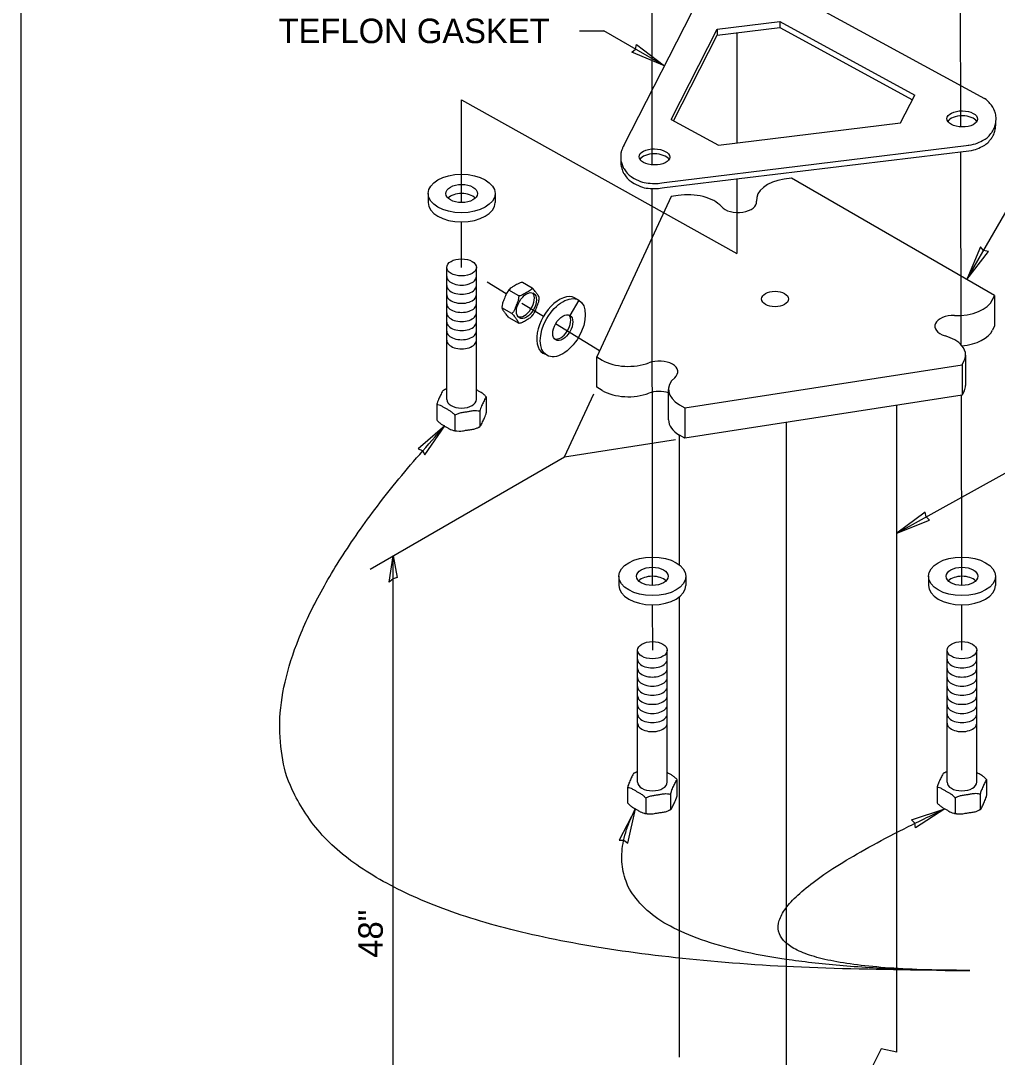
# Model space of a CAD drawing. Extents: x 99862 to 103151, y 99997 to 117076.
# Drawn here: x 99862 to 100500, y 115528 to 116205 of the extents above; entities that cross this region are included whole.
import ezdxf

# ---------------------------------------------------------------- set-up
doc = ezdxf.new("R2010")
doc.units = 0
for name, color, linetype in [('Level 1', 7, 'Continuous'), ('Level 12', 7, 'Continuous'), ('Level 13', 7, 'Continuous'), ('Level 15', 7, 'Continuous'), ('Level 20', 7, 'Continuous'), ('Level 4', 7, 'Continuous'), ('Level 6', 7, 'Continuous'), ('Level 8', 7, 'Continuous')]:
    doc.layers.add(name, color=color, linetype=linetype)

msp = doc.modelspace()

# ---------------------------------------------------------------- linework, layer by layer
at = {"layer": 'Level 1'}
msp.add_lwpolyline([(99862, 114999.5), (103151, 114999.5), (103151, 117075.5), (99862, 117075.5)], close=True, dxfattribs=at)
at = {"layer": 'Level 12'}
for p, q in [((100128.34, 116092.36), (100128.34, 116086.41)), ((100172.05, 116092.36), (100172.05, 116086.41)), ((100140.48, 115957.85), (100140.48, 116044.09)), ((100159.91, 115957.85), (100159.91, 116044.09)), ((100166.45, 115949.46), (100166.45, 115959.38)), ((100133.95, 115954.35), (100133.95, 115944.44)), ((100162.09, 115950), (100162.09, 115940.08)), ((100145.84, 115947.48), (100145.84, 115937.57)), ((100253.06, 115842.29), (100253.06, 115836.34)), ((100296.76, 115842.29), (100296.76, 115836.34)), ((100455.44, 115842.29), (100455.44, 115836.34)), ((100499.14, 115842.29), (100499.14, 115836.34)), ((100265.2, 115707.78), (100265.2, 115794.02)), ((100284.62, 115707.78), (100284.62, 115794.02)), ((100467.58, 115707.78), (100467.58, 115794.02)), ((100487, 115707.78), (100487, 115794.02)), ((100291.16, 115699.39), (100291.16, 115709.3)), ((100493.54, 115699.39), (100493.54, 115709.3)), ((100258.66, 115704.28), (100258.66, 115694.36)), ((100286.81, 115699.92), (100286.81, 115690.01)), ((100461.04, 115704.28), (100461.04, 115694.36)), ((100489.18, 115699.92), (100489.18, 115690.01)), ((100270.56, 115697.41), (100270.56, 115687.5)), ((100472.94, 115697.41), (100472.94, 115687.5))]:
    msp.add_line(p, q, dxfattribs=at)
for centre, major_axis in [((100150.2, 116092.36), (-21.85, 0)), ((100150.2, 116092.36), (-10.32, 0)), ((100150.2, 116044.09), (-9.71, 0)), ((100274.91, 115842.29), (-21.85, 0)), ((100477.29, 115842.29), (-21.85, 0)), ((100274.91, 115842.29), (-10.32, 0)), ((100477.29, 115842.29), (-10.32, 0)), ((100274.91, 115794.02), (-9.71, 0)), ((100477.29, 115794.02), (-9.71, 0))]:
    msp.add_ellipse(centre, major_axis=major_axis, ratio=0.57735, dxfattribs=at)
for centre, major_axis, start_param, end_param in [((100150.2, 116086.41), (-10.32, 0), 3.664192, 5.760586), ((100150.2, 116086.41), (21.85, 0), 3.141593, 6.283185), ((100150.2, 116038.15), (9.71, 0), 3.141588, 6.283185), ((100150.2, 116032.2), (9.71, 0), 3.141588, 6.283185), ((100150.2, 116026.25), (9.71, 0), 3.141588, 6.283185), ((100150.2, 116020.31), (9.71, 0), 3.141588, 6.283185), ((100150.2, 116014.36), (9.71, 0), 3.141588, 6.283185), ((100150.2, 116008.41), (9.71, 0), 3.141588, 6.283185), ((100150.2, 116002.46), (9.71, 0), 3.141588, 6.283185), ((100150.2, 115996.52), (9.71, 0), 3.141588, 6.283185), ((100150.2, 115957.85), (9.71, 0), 3.141593, 6.283185), ((100274.91, 115836.34), (-10.32, 0), 3.664192, 5.760586), ((100477.29, 115836.34), (-10.32, 0), 3.664192, 5.760586), ((100274.91, 115836.34), (21.85, 0), 3.141593, 6.283185), ((100477.29, 115836.34), (21.85, 0), 3.141593, 6.283185), ((100274.91, 115788.07), (9.71, 0), 3.141588, 6.283185), ((100477.29, 115788.07), (9.71, 0), 3.141588, 6.283185), ((100274.91, 115782.13), (9.71, 0), 3.141588, 6.283185), ((100477.29, 115782.13), (9.71, 0), 3.141588, 6.283185), ((100274.91, 115776.18), (9.71, 0), 3.141588, 6.283185), ((100477.29, 115776.18), (9.71, 0), 3.141588, 6.283185), ((100274.91, 115770.23), (9.71, 0), 3.141588, 6.283185), ((100477.29, 115770.23), (9.71, 0), 3.141588, 6.283185), ((100274.91, 115764.28), (9.71, 0), 3.141588, 6.283185), ((100477.29, 115764.28), (9.71, 0), 3.141588, 6.283185), ((100274.91, 115758.34), (9.71, 0), 3.141588, 6.283185), ((100477.29, 115758.34), (9.71, 0), 3.141588, 6.283185), ((100274.91, 115752.39), (9.71, 0), 3.141588, 6.283185), ((100477.29, 115752.39), (9.71, 0), 3.141588, 6.283185), ((100274.91, 115746.44), (9.71, 0), 3.141588, 6.283185), ((100477.29, 115746.44), (9.71, 0), 3.141588, 6.283185), ((100274.91, 115707.78), (9.71, 0), 3.141593, 6.283185), ((100477.29, 115707.78), (9.71, 0), 3.141593, 6.283185)]:
    msp.add_ellipse(centre, major_axis=major_axis, ratio=0.57735, start_param=start_param, end_param=end_param, dxfattribs=at)
for points, degree in [([(100138.18, 115963.68), (100138.12, 115963.65), (100138.05, 115963.59), (100137.43, 115962.93), (100136.72, 115961.31), (100136.12, 115960.03), (100135.53, 115958.74), (100134.82, 115957.29), (100134.15, 115955.14), (100134.04, 115954.75), (100133.95, 115954.35)], 3), ([(100138.9, 115964.1), (100138.68, 115963.98), (100138.47, 115963.86), (100138.24, 115963.72), (100138.21, 115963.7), (100138.18, 115963.68)], 3), ([(100140.48, 115964.77), (100140.13, 115964.65), (100139.78, 115964.52), (100139.27, 115964.29), (100139.09, 115964.2), (100138.9, 115964.1)], 3), ([(100166.45, 115959.38), (100166.19, 115959.72), (100165.88, 115960.05), (100164.07, 115961.82), (100162.12, 115962.86), (100160.5, 115963.8), (100160.31, 115963.91), (100160.11, 115964.02), (100159.91, 115964.14)], 3), ([(100166.45, 115959.38), (100166.35, 115959.37), (100166.24, 115959.28), (100165.58, 115958.57), (100164.86, 115956.95), (100164.27, 115955.67), (100163.67, 115954.39), (100162.96, 115952.94), (100162.3, 115950.79), (100162.19, 115950.39), (100162.09, 115950)], 3), ([(100145.84, 115947.48), (100145.58, 115947.83), (100145.28, 115948.16), (100143.47, 115949.92), (100141.52, 115950.96), (100139.9, 115951.9), (100138.27, 115952.84), (100136.32, 115954.05), (100134.51, 115954.37), (100134.21, 115954.39), (100133.95, 115954.35)], 3), ([(100162.09, 115950), (100161.74, 115950.14), (100161.32, 115950.23), (100158.85, 115950.56), (100156.19, 115950.07), (100153.97, 115949.72), (100151.75, 115949.38), (100149.09, 115949.05), (100146.61, 115947.95), (100146.2, 115947.73), (100145.84, 115947.48)], 3), ([(100133.95, 115944.44), (100134.21, 115944.09), (100134.51, 115943.76), (100136.32, 115942), (100138.27, 115940.96), (100139.9, 115940.02), (100141.5, 115939.09), (100143.41, 115937.91), (100144.94, 115937.61)], 3), ([(100162.22, 115940.13), (100162.28, 115940.17), (100162.34, 115940.22), (100162.96, 115940.88), (100163.67, 115942.51), (100164.27, 115943.79), (100164.86, 115945.07), (100165.58, 115946.52), (100166.24, 115948.67), (100166.35, 115949.07), (100166.45, 115949.46)], 3), ([(100144.93, 115937.61), (100145.68, 115937.46), (100146.44, 115937.35), (100147.18, 115937.26)], 2), ([(100144.94, 115937.61), (100144.96, 115937.6), (100144.98, 115937.6), (100145.28, 115937.54), (100145.58, 115937.52), (100145.84, 115937.57)], 3), ([(100145.84, 115937.57), (100146.2, 115937.43), (100146.61, 115937.34), (100147.05, 115937.28), (100147.12, 115937.27), (100147.18, 115937.26)], 3), ([(100147.18, 115937.26), (100149.25, 115937.03), (100151.82, 115937.51), (100153.97, 115937.84), (100156.19, 115938.18), (100158.85, 115938.51), (100161.12, 115939.53), (100161.31, 115939.62), (100161.49, 115939.72)], 3), ([(100161.49, 115939.71), (100161.71, 115939.83), (100161.92, 115939.95), (100162.16, 115940.09), (100162.19, 115940.11), (100162.22, 115940.13)], 3), ([(100161.49, 115939.72), (100161.7, 115939.83), (100161.9, 115939.95), (100162.09, 115940.08)], 2), ([(100162.09, 115940.08), (100162.13, 115940.09), (100162.17, 115940.1), (100162.22, 115940.13)], 2), ([(100262.89, 115713.61), (100262.83, 115713.57), (100262.77, 115713.52), (100262.15, 115712.86), (100261.43, 115711.23), (100260.84, 115709.95), (100260.25, 115708.67), (100259.53, 115707.22), (100258.87, 115705.07), (100258.76, 115704.67), (100258.66, 115704.28)], 3), ([(100263.62, 115714.03), (100263.4, 115713.91), (100263.19, 115713.79), (100262.95, 115713.65), (100262.92, 115713.63), (100262.89, 115713.61)], 3), ([(100265.2, 115714.7), (100264.84, 115714.58), (100264.49, 115714.44), (100263.99, 115714.22), (100263.8, 115714.13), (100263.62, 115714.03)], 3), ([(100291.16, 115709.3), (100290.9, 115709.65), (100290.6, 115709.98), (100288.79, 115711.74), (100286.84, 115712.78), (100285.21, 115713.72), (100285.02, 115713.83), (100284.82, 115713.95), (100284.62, 115714.06)], 3), ([(100465.27, 115713.61), (100465.21, 115713.57), (100465.15, 115713.52), (100464.53, 115712.86), (100463.81, 115711.23), (100463.22, 115709.95), (100462.62, 115708.67), (100461.91, 115707.22), (100461.25, 115705.07), (100461.14, 115704.67), (100461.04, 115704.28)], 3), ([(100465.99, 115714.03), (100465.77, 115713.91), (100465.56, 115713.79), (100465.33, 115713.65), (100465.3, 115713.63), (100465.27, 115713.61)], 3), ([(100467.58, 115714.7), (100467.22, 115714.58), (100466.87, 115714.44), (100466.36, 115714.22), (100466.18, 115714.13), (100466, 115714.03)], 3), ([(100493.54, 115709.3), (100493.28, 115709.65), (100492.97, 115709.98), (100491.16, 115711.74), (100489.22, 115712.78), (100487.59, 115713.72), (100487.4, 115713.83), (100487.2, 115713.95), (100487, 115714.06)], 3), ([(100286.81, 115699.92), (100286.9, 115700.32), (100287.01, 115700.72), (100287.68, 115702.86), (100288.39, 115704.32), (100288.98, 115705.6), (100289.58, 115706.88), (100290.29, 115708.5), (100290.95, 115709.21), (100291.07, 115709.29), (100291.16, 115709.3)], 3), ([(100493.54, 115709.3), (100493.44, 115709.29), (100493.33, 115709.21), (100492.67, 115708.5), (100491.96, 115706.88), (100491.36, 115705.6), (100490.77, 115704.32), (100490.05, 115702.86), (100489.39, 115700.72), (100489.28, 115700.32), (100489.18, 115699.92)], 3), ([(100258.66, 115704.28), (100258.92, 115704.32), (100259.23, 115704.3), (100261.04, 115703.98), (100262.99, 115702.77), (100264.61, 115701.83), (100266.24, 115700.89), (100268.18, 115699.85), (100269.99, 115698.08), (100270.3, 115697.75), (100270.56, 115697.41)], 3), ([(100270.56, 115697.41), (100270.91, 115697.66), (100271.33, 115697.88), (100273.8, 115698.98), (100276.46, 115699.31), (100278.68, 115699.65), (100280.9, 115699.99), (100283.56, 115700.49), (100286.04, 115700.15), (100286.45, 115700.06), (100286.81, 115699.92)], 3), ([(100472.94, 115697.41), (100472.68, 115697.75), (100472.37, 115698.08), (100470.56, 115699.85), (100468.61, 115700.89), (100466.99, 115701.83), (100465.36, 115702.77), (100463.41, 115703.98), (100461.6, 115704.3), (100461.3, 115704.32), (100461.04, 115704.28)], 3), ([(100489.18, 115699.92), (100488.83, 115700.06), (100488.41, 115700.15), (100485.94, 115700.49), (100483.28, 115699.99), (100481.06, 115699.65), (100478.84, 115699.31), (100476.18, 115698.98), (100473.71, 115697.88), (100473.29, 115697.66), (100472.94, 115697.41)], 3), ([(100258.66, 115694.36), (100258.92, 115694.02), (100259.23, 115693.69), (100261.04, 115691.92), (100262.99, 115690.88), (100264.61, 115689.94), (100266.21, 115689.02), (100268.13, 115687.83), (100269.65, 115687.53)], 3), ([(100286.93, 115690.06), (100286.99, 115690.09), (100287.05, 115690.15), (100287.68, 115690.81), (100288.39, 115692.43), (100288.98, 115693.71), (100289.58, 115695), (100290.29, 115696.45), (100290.95, 115698.6), (100291.07, 115698.99), (100291.16, 115699.39)], 3), ([(100461.04, 115694.36), (100461.3, 115694.02), (100461.6, 115693.69), (100463.41, 115691.92), (100465.36, 115690.88), (100466.99, 115689.94), (100468.59, 115689.02), (100470.5, 115687.83), (100472.03, 115687.53)], 3), ([(100489.31, 115690.06), (100489.37, 115690.09), (100489.43, 115690.15), (100490.05, 115690.81), (100490.77, 115692.43), (100491.36, 115693.71), (100491.96, 115695), (100492.67, 115696.45), (100493.33, 115698.6), (100493.44, 115698.99), (100493.54, 115699.39)], 3), ([(100269.65, 115687.53), (100270.4, 115687.39), (100271.16, 115687.27), (100271.9, 115687.19)], 2), ([(100271.9, 115687.19), (100273.96, 115686.96), (100276.53, 115687.43), (100278.68, 115687.77), (100280.9, 115688.11), (100283.56, 115688.44), (100285.84, 115689.45), (100286.02, 115689.54), (100286.21, 115689.64)], 3), ([(100286.21, 115689.64), (100286.43, 115689.76), (100286.64, 115689.88), (100286.87, 115690.02), (100286.9, 115690.04), (100286.93, 115690.06)], 3), ([(100472.03, 115687.53), (100472.78, 115687.39), (100473.53, 115687.27), (100474.28, 115687.19)], 2), ([(100474.28, 115687.19), (100476.34, 115686.96), (100478.91, 115687.43), (100481.06, 115687.77), (100483.28, 115688.11), (100485.94, 115688.44), (100488.22, 115689.45), (100488.4, 115689.54), (100488.59, 115689.64)], 3), ([(100488.58, 115689.64), (100488.8, 115689.76), (100489.02, 115689.88), (100489.25, 115690.02), (100489.28, 115690.04), (100489.31, 115690.06)], 3)]:
    msp.add_open_spline(points, degree=degree, dxfattribs=at)
at = {"layer": 'Level 13'}
for p, q in [((100196.43, 116030.6), (100189.99, 116034.32)), ((100187.51, 116025.45), (100181.07, 116029.17)), ((100183.05, 116013.96), (100176.61, 116017.67)), ((100226.77, 116022.74), (100220.99, 116012.72)), ((100181.07, 116011.33), (100187.51, 116007.61))]:
    msp.add_line(p, q, dxfattribs=at)
for centre, major_axis in [((100192.6, 116019.17), (-4.63, -8.02)), ((100216.36, 116004.7), (-10.41, -18.04)), ((100216.36, 116004.7), (-4.63, -8.02))]:
    msp.add_ellipse(centre, major_axis=major_axis, ratio=0.57735, dxfattribs=at)
for centre, major_axis, start_param, end_param in [((100191.25, 116020.2), (-4.63, -8.02), 0.083455, 2.907882), ((100214.04, 116005.98), (-10.41, -18.04), 3.042453, 6.404476), ((100215.01, 116005.73), (-4.63, -8.02), 0.083455, 2.907882)]:
    msp.add_ellipse(centre, major_axis=major_axis, ratio=0.57735, start_param=start_param, end_param=end_param, dxfattribs=at)
for points, degree in [([(100189.99, 116034.32), (100189.67, 116034.28), (100189.34, 116034.21), (100187.52, 116033.69), (100186.11, 116032.82), (100184.89, 116032.11), (100183.69, 116031.42), (100182.2, 116030.62), (100181.44, 116029.74)], 3), ([(100180.37, 116028.41), (100179.44, 116027.16), (100178.79, 116025.31), (100178.2, 116023.79), (100177.59, 116022.22), (100176.81, 116020.37), (100176.61, 116018.51), (100176.6, 116018.36), (100176.6, 116018.2)], 3), ([(100181.44, 116029.74), (100181.06, 116029.31), (100180.7, 116028.86), (100180.37, 116028.41)], 2), ([(100187.51, 116025.45), (100187.54, 116025.13), (100187.53, 116024.78), (100187.31, 116022.76), (100186.53, 116020.9), (100185.92, 116019.33), (100185.31, 116017.76), (100184.63, 116015.85), (100183.49, 116014.37), (100183.27, 116014.13), (100183.05, 116013.96)], 3), ([(100196.43, 116030.6), (100196.36, 116030.42), (100196.24, 116030.23), (100195.35, 116029.17), (100193.83, 116028.36), (100192.61, 116027.66), (100191.39, 116026.95), (100189.99, 116026.08), (100188.16, 116025.56), (100187.83, 116025.49), (100187.51, 116025.45)], 3), ([(100200.91, 116024.36), (100200.91, 116024.41), (100200.89, 116024.47), (100200.7, 116025.12), (100199.91, 116026.19), (100199.3, 116027.06), (100198.69, 116027.93), (100198.02, 116028.93), (100196.87, 116030.17), (100196.65, 116030.39), (100196.43, 116030.6)], 3), ([(100197.13, 116013.52), (100198.06, 116014.77), (100198.71, 116016.62), (100199.3, 116018.14), (100199.91, 116019.71), (100200.7, 116021.56), (100200.89, 116023.42), (100200.9, 116023.57), (100200.91, 116023.73)], 3), ([(100200.91, 116023.73), (100200.91, 116023.92), (100200.91, 116024.1), (100200.91, 116024.3), (100200.91, 116024.33), (100200.91, 116024.36)], 3), ([(100176.59, 116017.57), (100176.6, 116017.52), (100176.61, 116017.46), (100176.81, 116016.81), (100177.59, 116015.74), (100178.2, 116014.87), (100178.81, 116014), (100179.49, 116013), (100180.63, 116011.76), (100180.85, 116011.54), (100181.07, 116011.33)], 3), ([(100183.05, 116013.96), (100183.27, 116013.74), (100183.49, 116013.52), (100184.63, 116012.29), (100185.31, 116011.28), (100185.92, 116010.41), (100186.53, 116009.55), (100187.31, 116008.48), (100187.53, 116007.78), (100187.54, 116007.68), (100187.51, 116007.61)], 3), ([(100187.51, 116007.61), (100187.83, 116007.65), (100188.16, 116007.72), (100189.99, 116008.24), (100191.39, 116009.11), (100192.61, 116009.82), (100193.81, 116010.51), (100195.3, 116011.31), (100196.07, 116012.18)], 3), ([(100196.07, 116012.19), (100196.44, 116012.62), (100196.8, 116013.07), (100197.13, 116013.52)], 2)]:
    msp.add_open_spline(points, degree=degree, dxfattribs=at)
at = {"layer": 'Level 15'}
for p, q in [((100476.45, 116135.88), (100475.61, 116477.49)), ((100274.34, 116329.01), (100274.57, 116111.09)), ((100227.26, 116198.6), (100243.26, 116198.6)), ((100282.8, 116175.77), (100243.26, 116198.6)), ((100330.1, 116197.43), (100330.1, 116125.34)), ((100150.2, 116086.4), (100150.2, 116153.6)), ((100476.8, 115993.44), (100476.49, 116119.57)), ((100480.53, 116036.22), (100526.41, 116115.68)), ((100330.1, 116101.97), (100330.1, 116053.13)), ((100274.59, 116095.68), (100274.87, 115836.33)), ((100150.2, 116044.09), (100150.2, 116073.8)), ((100179.42, 116026.78), (100167, 116034.35)), ((100203.64, 116012.01), (100189.57, 116020.59)), ((100240.45, 115989.57), (100211.61, 116007.15)), ((100217.55, 115920.4), (100236.61, 115961.46)), ((100477.19, 115836.33), (100476.88, 115960.52)), ((100217.55, 115920.4), (100290.04, 115931.61)), ((100434.78, 115870.52), (100546.07, 115932.25)), ((100090.53, 115847.06), (100217.55, 115920.4)), ((100274.88, 115823.72), (100274.91, 115794.02)), ((100477.29, 115794.02), (100477.22, 115823.72)), ((100466.36, 115584.83), (100482.36, 115584.83))]:
    msp.add_line(p, q, dxfattribs=at)
for points in [[(100282.8, 116175.77), (100261.54, 116184.6), (100263.94, 116186.66), (100264.52, 116189.77)], [(100480.53, 116036.22), (100494.53, 116054.5), (100491.42, 116055.08), (100489.36, 116057.48)], [(100139.22, 115940.62), (100121.77, 115925.6), (100124.7, 115924.39), (100126.22, 115921.62)], [(100434.78, 115870.52), (100456.17, 115879.04), (100453.79, 115881.13), (100453.26, 115884.25)], [(100105.5, 115855.71), (100108.17, 115841.52), (100105.5, 115840.71), (100102.83, 115838.43)], [(100263.81, 115690.4), (100253.2, 115669.97), (100256.36, 115669.94), (100258.81, 115667.93)], [(100466.19, 115690.4), (100446.86, 115677.89), (100446.53, 115681.04), (100444.29, 115683.27)]]:
    msp.add_lwpolyline(points, close=True, dxfattribs=at)
for points in [[(100150.2, 116153.6), (100330.1, 116053.13)], [(100105.5, 115437.89), (100105.5, 115855.71)]]:
    msp.add_lwpolyline(points, dxfattribs=at)
for points in [[(100466.36, 115584.83), (99814.76, 115584.83), (100139.09, 115940.48)], [(100482.36, 115584.83), (100209.96, 115584.83), (100263.81, 115690.4)], [(100482.36, 115584.83), (100240.37, 115584.83), (100466.19, 115690.4)]]:
    msp.add_open_spline(points, degree=2, dxfattribs=at)
at = {"layer": 'Level 4'}
for p, q in [((100362.49, 115487.9), (100362.49, 115942.72)), ((100424.47, 115533.65), (100412.67, 115510.03)), ((100434.78, 115531.35), (100424.47, 115533.65))]:
    msp.add_line(p, q, dxfattribs=at)
for points in [[(100434.78, 115531.35), (100434.78, 115954.01)], [(100292.43, 115934.68), (100292.43, 115849.65)], [(100292.43, 115829.04), (100292.43, 115528.12)]]:
    msp.add_lwpolyline(points, dxfattribs=at)
at = {"layer": 'Level 6'}
for p, q in [((100365.77, 116102.48), (100360.96, 116101.73)), ((100498.58, 116025.8), (100365.77, 116102.48)), ((100287.21, 116090.32), (100238.6, 115985.58)), ((100291.72, 116091.02), (100287.21, 116090.32)), ((100497.29, 116023.02), (100498.58, 116025.8)), ((100498.58, 116025.8), (100498.58, 116005.98)), ((100498.58, 116005.98), (100497.29, 116003.2)), ((100238.6, 115985.58), (100242.13, 115983.55)), ((100238.6, 115965.76), (100238.6, 115985.58)), ((100479.65, 115986.85), (100479.65, 115967.03)), ((100296.12, 115952.38), (100477.53, 115980.44)), ((100477.53, 115980.44), (100478.82, 115983.22)), ((100477.53, 115980.44), (100477.53, 115960.62)), ((100242.13, 115963.72), (100238.6, 115965.76)), ((100285.48, 115944.5), (100285.48, 115964.33)), ((100477.53, 115960.62), (100296.12, 115932.55)), ((100478.82, 115963.4), (100477.53, 115960.62)), ((100292.59, 115954.41), (100296.12, 115952.38)), ((100296.12, 115952.38), (100296.12, 115932.55)), ((100296.12, 115932.55), (100292.59, 115934.59))]:
    msp.add_line(p, q, dxfattribs=at)
for centre, major_axis, start_param, end_param in [((100367.25, 116088.19), (-24.28, 0), 4.974189, 6.343627), ((100298.31, 116077.53), (-24.28, 0), 3.604667, 4.987015), ((100330.89, 116086.92), (-12.14, 0), 0.463321, 3.201871), ((100473.84, 116026.65), (-24.28, 0), 1.510356, 2.879794), ((100471.64, 116005.66), (-12.14, 0), 4.652112, 7.390662), ((100455.37, 115986.85), (-24.28, 0), 3.591411, 4.249233), ((100473.84, 116006.83), (-24.28, 0), 1.711023, 2.879794), ((100455.37, 115986.85), (-24.28, 0), 3.141593, 3.591411), ((100455.37, 115986.85), (-24.28, 0), 2.879794, 3.141593), ((100259.3, 115993.46), (-24.28, 0), 0.785398, 2.154673), ((100279.38, 115975.92), (-12.14, 0), 2.557552, 5.296429), ((100309.76, 115964.33), (-24.28, 0), 5.699308, 7.068583), ((100259.3, 115973.64), (-24.28, 0), 0.785398, 2.154673), ((100279.38, 115956.09), (-12.14, 0), 4.185432, 5.296429), ((100455.37, 115967.03), (-24.28, 0), 2.879794, 3.141593), ((100309.76, 115944.5), (-24.28, 0), 0, 0.785398)]:
    msp.add_ellipse(centre, major_axis=major_axis, ratio=0.57735, start_param=start_param, end_param=end_param, dxfattribs=at)
msp.add_ellipse((100355.08, 116023.46), major_axis=(-8.75, 0), ratio=0.57735, dxfattribs=at)
at = {"layer": 'Level 8'}
for p, q in [((100343.68, 116235.21), (100491.99, 116154.4)), ((100256.21, 116123.8), (100309.39, 116227.74)), ((100317.3, 116199.66), (100358.24, 116204.7)), ((100317.3, 116195.85), (100358.24, 116200.89)), ((100358.24, 116204.7), (100358.24, 116200.89)), ((100358.24, 116204.7), (100446.46, 116156.63)), ((100358.24, 116200.89), (100444.94, 116153.64)), ((100287.12, 116140.7), (100317.3, 116199.66)), ((100288.65, 116139.87), (100317.3, 116195.85)), ((100317.3, 116199.66), (100317.3, 116195.85)), ((100437.2, 116138.51), (100446.46, 116156.63)), ((100287.12, 116140.7), (100318.03, 116123.85)), ((100318.03, 116123.85), (100437.2, 116138.51)), ((100282.55, 116099.51), (100481.84, 116124.03)), ((100282.86, 116096.29), (100481.84, 116120.22)), ((100254.21, 116115.05), (100254.21, 116112.86))]:
    msp.add_line(p, q, dxfattribs=at)
for centre in [(100477.51, 116141.12), (100276.23, 116116.28)]:
    msp.add_ellipse(centre, major_axis=(10.01, -0.15), ratio=0.526809, dxfattribs=at)
for centre in [(100477.59, 116137.82), (100276.3, 116112.98)]:
    msp.add_ellipse(centre, major_axis=(10.01, -0.15), ratio=0.526809, start_param=0.33789, end_param=2.844208, dxfattribs=at)
for points, degree in [([(100499.58, 116140.79), (100499.61, 116142.65), (100499.28, 116144.48), (100498.11, 116147.72), (100497.29, 116149.13), (100495.04, 116152.07), (100493.52, 116153.38), (100491.99, 116154.4)], 3), ([(100481.36, 116123.97), (100484.27, 116124.3), (100487.17, 116125.09), (100492.08, 116127.58), (100494.23, 116129.05), (100497.04, 116132.53), (100497.9, 116133.9), (100499.17, 116137.12), (100499.56, 116138.93), (100499.58, 116140.79)], 3), ([(100481.84, 116120.22), (100484.52, 116120.59), (100487.17, 116121.36), (100491.86, 116123.74), (100494.01, 116125.21), (100496.83, 116128.68), (100497.68, 116130.06), (100498.95, 116133.27), (100499.34, 116135.09), (100499.37, 116136.95)], 3), ([(100499.37, 116136.95), (100499.37, 116137.39), (100499.36, 116137.82), (100499.33, 116138.25)], 2), ([(100256.21, 116123.8), (100255.86, 116123.18), (100255.53, 116122.52), (100254.63, 116120.22), (100254.24, 116118.4), (100254.18, 116114.7), (100254.52, 116112.87), (100255.68, 116109.64), (100256.5, 116108.24), (100259.2, 116104.69), (100261.29, 116103.17), (100267.45, 116099.81), (100271.68, 116098.99), (100278.19, 116098.9), (100280.37, 116099.06), (100282.55, 116099.51)], 3), ([(100254.21, 116113.23), (100254.19, 116111.39), (100254.52, 116109.57), (100255.69, 116106.35), (100256.5, 116104.95), (100259.2, 116101.4), (100261.3, 116099.87), (100267.45, 116096.51), (100271.68, 116095.7), (100278.29, 116095.6), (100280.58, 116095.78), (100282.86, 116096.29)], 3)]:
    msp.add_open_spline(points, degree=degree, dxfattribs=at)

# ---------------------------------------------------------------- texts
at = {"layer": 'Level 20'}
msp.add_text('TEFLON GASKET', height=16, dxfattribs=at).set_placement((100030.6, 116190.6))
msp.add_text('48"', height=16, rotation=90, dxfattribs=at).set_placement((100098.69, 115593.12))

doc.saveas('drawing.dxf')
